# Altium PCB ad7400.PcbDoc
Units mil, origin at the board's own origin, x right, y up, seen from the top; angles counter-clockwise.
Board outline 2285.03 x 910.03 mil, 2 copper layers (Top Layer, Bottom Layer); 12 components, 9 nets, 44 pads, 2 vias.
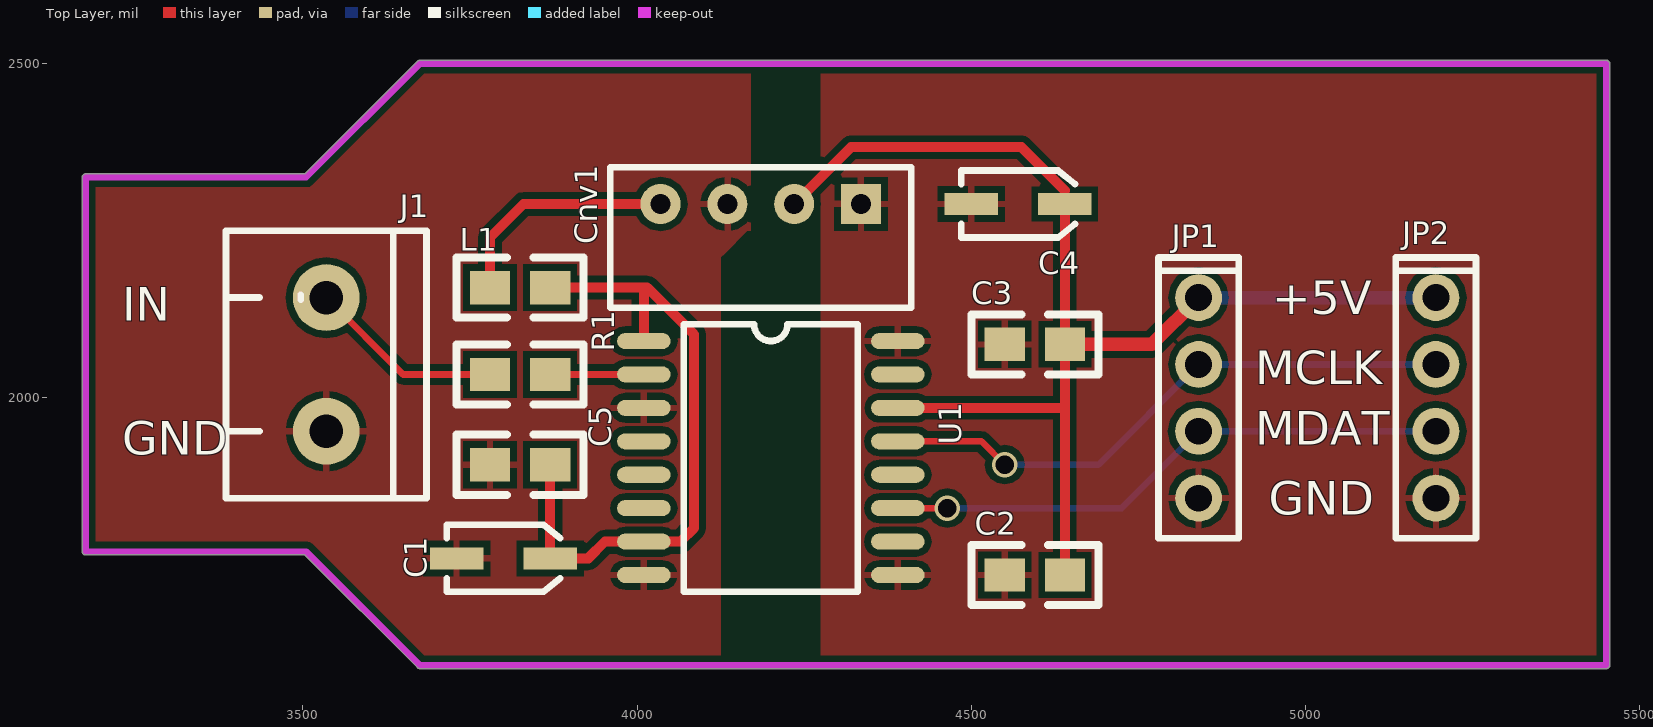
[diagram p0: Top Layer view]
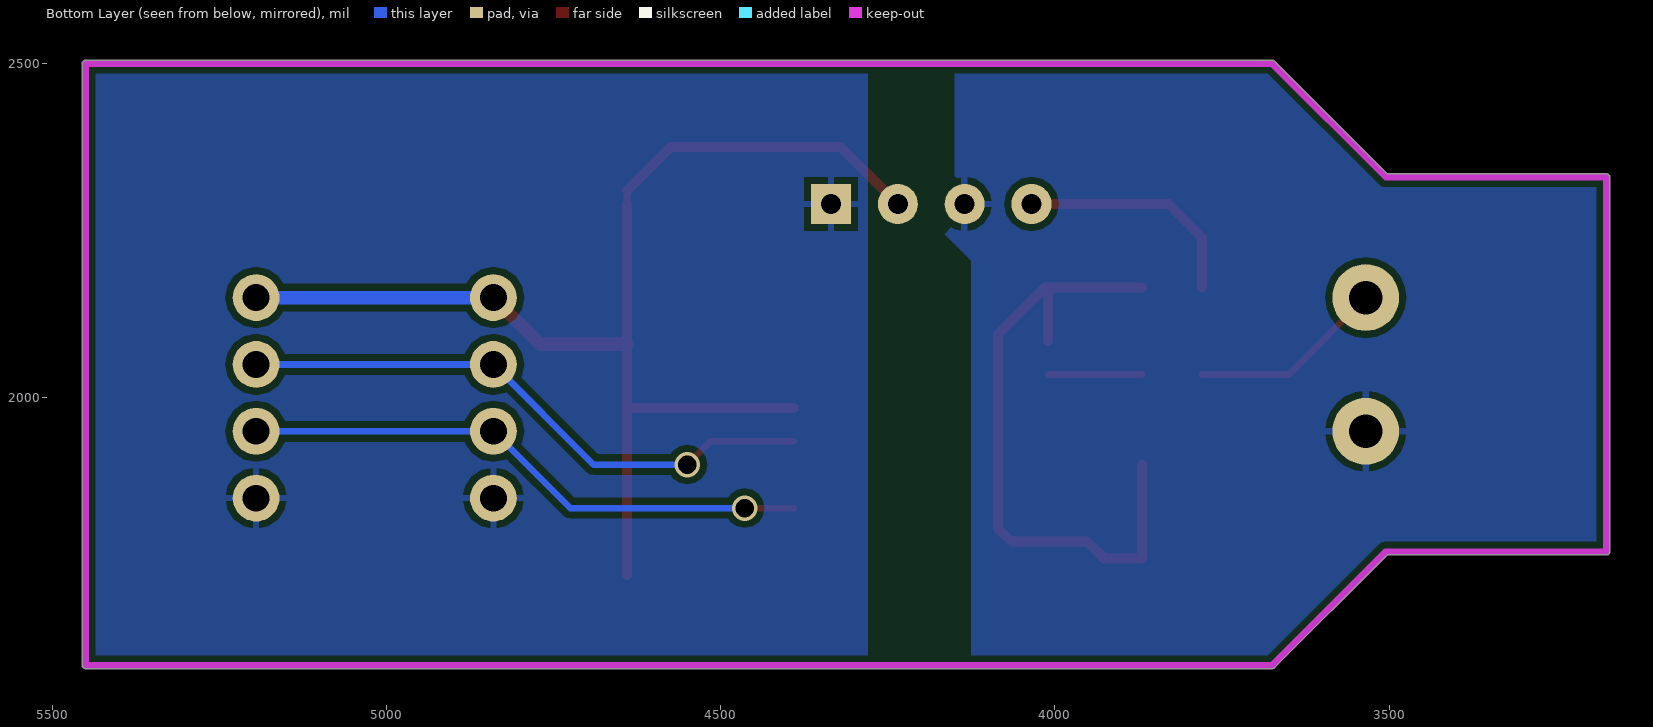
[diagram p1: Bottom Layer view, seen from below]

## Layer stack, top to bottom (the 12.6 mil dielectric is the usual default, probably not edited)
Top Layer: signal copper 1.4
Dielectric: dielectric 12.6, FR-4, Dk 4.8
Bottom Layer: signal copper 1.4

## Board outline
3169.99,1770 ccw(c3175,1770) 3175,1764.98 3502.92,1764.98 3671.45,1596.45 3671.44,1596.47 ccw(c3675,1600) 3675,1594.98 5450,1594.98 ccw(c5450,1600) 5455.02,1600 5455.02,2500 ccw(c5450,2500) 5450,2505.01 3675,2505.01 ccw(c3675,2500) 3671.44,2503.53 3671.45,2503.55 3502.92,2335.01 3175,2335.01 ccw(c3175,2330) 3169.99,2330

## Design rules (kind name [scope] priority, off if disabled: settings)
Clearance [All] p1: gap=10
PolygonConnect [All] p1: connectstyle=Relief reliefconductorwidth=10 reliefentries=4 polygonreliefangle="90 Angle"
RoutingVias [All] p1: holewidth=28 width=50 viastyle="Through Hole" minholewidth=28 minwidth=50 maxholewidth=28 maxwidth=50
SilkscreenOverComponentPads [All] p1: minsilkscreentomaskgap=10
SolderMaskExpansion [All] p1: expansion=4
Width [All] p1: maxlimit=10 minlimit=10 preferedwidth=10
27 further rules are at their usual default settings.

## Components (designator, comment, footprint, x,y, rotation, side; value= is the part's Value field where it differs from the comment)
C1 "10uF" CE_SMD_W 3870,1760 r180 top
C2 "100nF" 0805 4640,1735 r180 top
C3 "100nF" 0805 4640,2080 r180 top
C4 "10uF" CE_SMD_W 4640,2290 r180 top
C5 "100nF" 0805 3870,1900 r180 top
Cnv1 "AM1S-0505SZ" SIP4_AM1S 4335,2290 r180 top
J1 "CON2" ARK2 3535,2150 r180 top
JP1 "4 HEADER" GP4 4840,2150 r270 top
JP2 "4 HEADER" GP4 5195,2150 r270 top
L1 "INDUCTOR" 0805 3870,2165 r180 top
R1 "2,2k" 0805 3780,2035 r0 top
U1 "AD7400" SOL-16 4010,2085 r0 top

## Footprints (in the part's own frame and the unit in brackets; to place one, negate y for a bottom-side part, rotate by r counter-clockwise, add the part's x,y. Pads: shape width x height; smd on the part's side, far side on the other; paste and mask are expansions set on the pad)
0805 [mil]
  rect 60x50 smd: 1(0,0) 2(90,0)
  silkscreen extent -50,-45 140,45
ARK2 [mil]
  round 100 hole 50: 1(0,0) 2(0,200)
  silkscreen extent -150,-100 150,300
CE_SMD_W [mil]
  rect 80x33 smd: 1(0,0) 2(140,0)
  silkscreen extent -15,-50 155,50
GP4 [mil]
  round 70 hole 40: 1(0,0) 2(100,0) 3(200,0) 4(300,0)
  silkscreen extent -60,-60 360,60
SIP4_AM1S [mil]
  rect 60x60 hole 30: 1(0,0)
  round 60 hole 30: 2(100,0) 3(200,0) 4(300,0)
  silkscreen extent -75,-55 375,155
SOL-16 [mil]
  oval 80x24 smd: 1(0,0) 2(0,-50) 3(0,-100) 4(0,-150) 5(0,-200) 6(0,-250) 7(0,-300) 8(0,-350) 9(380,-350) 10(380,-300) 11(380,-250) 12(380,-200) 13(380,-150) 14(380,-100) 15(380,-50) 16(380,0)
  silkscreen extent 60,-375 320,25

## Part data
C1 C4: library part CP, "Capacitor"
C2 C3 C5: library part Cap, "Capacitor"
J1: "Connector"
JP1 JP2: library part "HEADER 4", "4 Pin Header"
R1: library part RES2

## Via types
v1: diameter 38, hole 28, Top Layer to Bottom Layer, 2 vias

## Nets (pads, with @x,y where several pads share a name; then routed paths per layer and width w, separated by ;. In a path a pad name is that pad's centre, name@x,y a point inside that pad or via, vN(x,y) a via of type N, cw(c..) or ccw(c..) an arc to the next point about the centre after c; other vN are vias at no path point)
+VCC1: C2.1 C3.1 C4.1 Cnv1.2 JP1.1 JP2.1 U1.14 | length 1876.1
  Top Layer w10: C4.1 4640,2310
  Top Layer w15: Cnv1.2 4320,2375 4575,2375 4640,2310 ; U1.14 4640,1985 ; C2.1 C3.1 C4.1
  Top Layer w20: C3.1 4770,2080 JP1.1
  Bottom Layer w20: JP1.1 JP2.1
GND1: C1.2 C5.2 Cnv1.3 J1.2 U1.3 U1.8
GND2: C2.2 C3.2 C4.2 Cnv1.1 JP1.4 JP2.4 U1.9 U1.16
NetC1_1: C1.1 C5.1 L1.1 U1.1 U1.7 | length 987.6
  Top Layer w15: C5.1 C1.1 3927,1760 3952,1785 U1.7 4065,1785 4085,1805 4085,2095 4015,2165 3965,2165 L1.1 ; U1.1 4010,2165
NetCnv1_4: Cnv1.4 L1.2 | length 350.7
  Top Layer w15: L1.2 3780,2240 3830,2290 Cnv1.4
NetJ1_1: J1.1 R1.1 | length 292.6
  Top Layer w10: J1.1 3650,2035 R1.1
NetJP1_2: JP1.2 JP2.2 U1.13 | length 881.6
  Top Layer w10: U1.13 4515,1935 v1(4550,1900)
  Bottom Layer w10: v1(4550,1900) 4690,1900 JP1.2 JP2.2
NetJP1_3: JP1.3 JP2.3 U1.11 | length 852.6
  Top Layer w10: U1.11 v1(4464,1835)
  Bottom Layer w10: v1(4464,1835) 4725,1835 JP1.3 JP2.3
NetR1_2: R1.2 U1.2 | length 140
  Top Layer w10: R1.2 U1.2
pads on no net: U1.4 U1.5 U1.6 U1.10 U1.12 U1.15

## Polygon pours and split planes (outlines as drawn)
GND1 on Bottom Layer "Top Layer-No Net" (solid, remove dead copper, pour order 2): 3165,2345 3170,2340 3170,1750 3505,1750 3510,1755 3675,1590 3685,1590 4120,1590 4125,1585 4125,2195 4125,2205 4165,2245 4150,2260 4150,2515 3675,2515 3670,2510 3500,2340 3495,2340 3170,2340 3165,2345
GND2 on Bottom Layer "Top Layer-No Net" (solid, remove dead copper, pour order 8): 4275,2515 4280,2510 4280,1585 5455,1585 5465,1595 5450,1610 5450,2515 4275,2515
GND1 on Top Layer "Top Layer-No Net" (solid, remove dead copper, pour order 4): 3165,1750 3500,1750 3505,1750 3670,1585 4125,1585 4125,2210 4130,2215 4165,2250 4170,2250 4170,2490 4145,2515 4140,2510 3670,2510 3670,2505 3500,2335 3170,2335 3170,1755 3165,1750
GND2 on Top Layer "Top Layer-No Net" (solid, remove dead copper, pour order 6): 4275,2510 4275,1585 5455,1585 5460,1590 5465,1595 5465,2510 4275,2510

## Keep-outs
Keep-Out Layer:
  lines w10: 5450,1995 5450,2500 3675,2500 3505,2330 3175,2330 3175,2050 3175,1770 3505,1770 3675,1600 5450,1600 5450,2000

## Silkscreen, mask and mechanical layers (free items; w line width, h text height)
Top Overlay:
  text "+5V" at 4950,2125 h50
  text "IN" at 3230,2115 h50
  text "MCLK" at 4925,2020 h50
  text "MDAT" at 4925,1930 h50
  text "GND" at 3230,1915 h50
  text "GND" at 4945,1825 h50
